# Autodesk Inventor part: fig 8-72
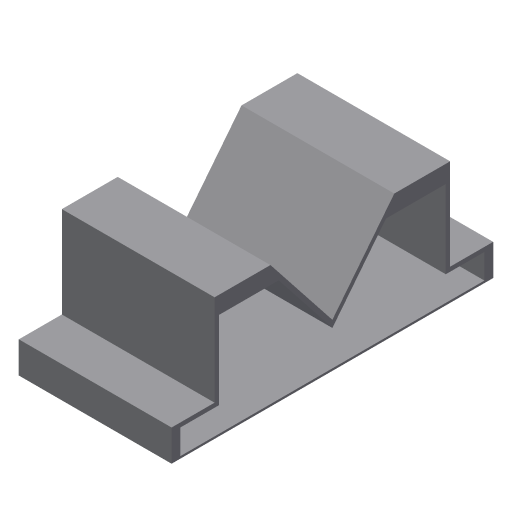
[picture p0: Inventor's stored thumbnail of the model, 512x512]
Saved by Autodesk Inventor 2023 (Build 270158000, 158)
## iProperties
Created: 2002-01
Part Number: fig 8-72
Document SubType Name: Modeling
Designer: ***
Density: 1 g/cm^3
Material: Generic
Appearance: Default
Control State: 0
Master: False
Checked Out: False
Shininess: 77.0
Length Units: 11269
Angle Units: 11279
Time Units: 11290
Mass Units: 11283
Length Display Precision: 3
Angle Display Precision: 2
Density: 0.0
Volumn: 0.0
Area: 0.0
PropertySet Name: Model Information
Author: ***
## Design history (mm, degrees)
node "Sketch1"
sketch "Sketch2"
  geometry: L1 (0, 0)-(-14.184, 17.961); L2 (-14.184, 17.961)-(-26.987, 17.961); L3 (-26.987, 17.961)-(-26.987, -2.947); L4 (-26.987, -2.947)-(-36.842, -2.947); L5 (-36.842, -2.947)-(-36.842, -10.132); L6 (26.987, 17.961)-(26.987, -2.947); L7 (14.184, 17.961)-(26.987, 17.961); L8 (26.987, -2.947)-(36.842, -2.947); L9 (36.842, -10.132)-(-36.842, -10.132); L10 (36.842, -2.947)-(36.842, -10.132); L11 (0, 0)-(14.184, 17.961)
  constraints: 22 end point, 2 horizontal, 2 parallel, 1 perpendicular
extrude "Extrusion1" new body sketch "Sketch2" distance "d0" = 35; taper "d1" = 0 deg
shell "Shell3" dims "d8" = 4, "d9" = 4, "d10" = 2, "d11" = 2, "d12" = 0.5, "d13" = 1
body "Solid1"
